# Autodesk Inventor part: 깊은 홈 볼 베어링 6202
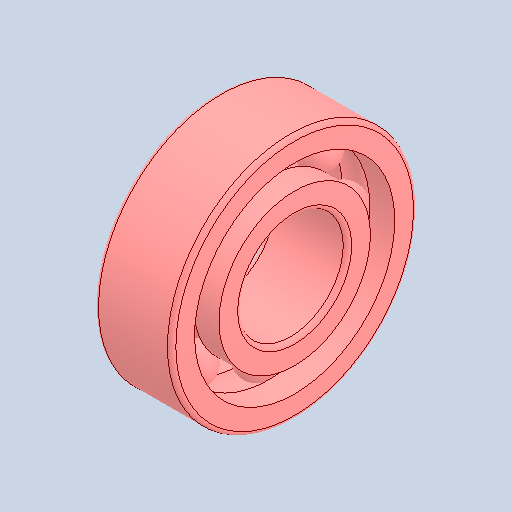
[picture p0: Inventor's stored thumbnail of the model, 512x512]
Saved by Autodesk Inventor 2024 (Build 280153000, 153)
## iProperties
Created: 2024-10
Part Number: 깊은 홈 볼 베어링 6202
Material: 강철, 연강
Description: 깊은 그루브 볼 베어링
Document SubType Name: Modeling
Designer: user
Density: 7.85 g/cm^3
Appearance: 기본값
Author: jhkim
Sending System: Autodesk Inventor 2025
Preprocessor: ST-DEVELOPER v20
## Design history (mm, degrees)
feature "Solid1"
feature "Solid1:1"
feature "Solid1:2"
feature "Solid1:3"
feature "Solid1:4"
feature "Solid1:5"
feature "Solid1:6"
feature "Solid1:7"
feature "Solid1:8"
feature "Solid1:9"
node "솔리드1"
node "솔리드2"
node "솔리드3"
node "솔리드4"
node "솔리드5"
node "솔리드6"
node "솔리드7"
node "솔리드8"
node "솔리드9"
node "솔리드10"
